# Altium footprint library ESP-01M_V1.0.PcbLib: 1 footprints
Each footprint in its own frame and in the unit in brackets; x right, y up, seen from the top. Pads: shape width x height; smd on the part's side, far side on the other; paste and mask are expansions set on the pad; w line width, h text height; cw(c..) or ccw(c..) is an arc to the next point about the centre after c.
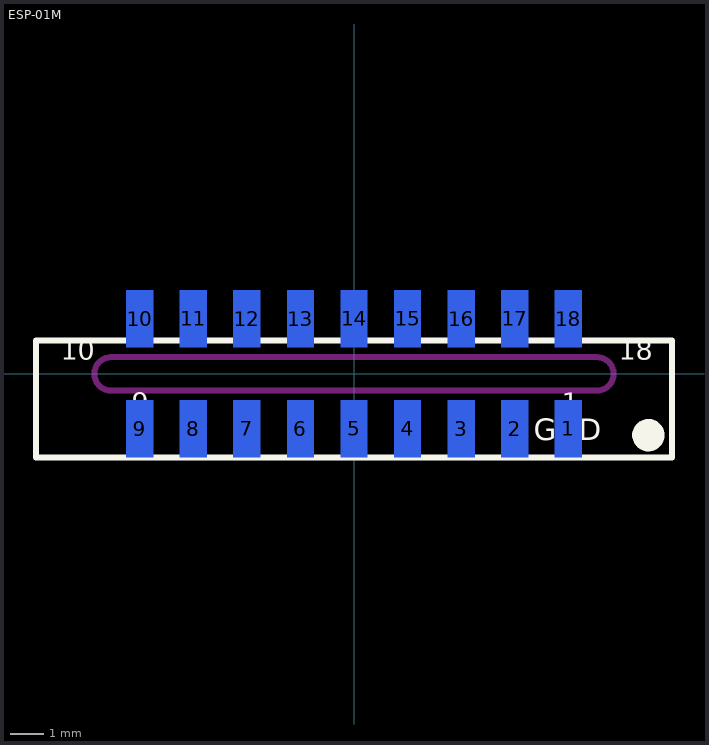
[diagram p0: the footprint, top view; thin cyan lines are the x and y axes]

## ESP-01M [mm]
pads (18):
  rect 0.8x1.7 smd far side: 1(6.4,-1.643) 2(4.8,-1.643) 3(3.2,-1.643) 4(1.6,-1.643) 5(0,-1.643) 6(-1.6,-1.643) 7(-3.2,-1.643) 8(-4.8,-1.643) 9(-6.4,-1.643) 10(-6.4,1.643) 11(-4.8,1.643) 12(-3.2,1.643) 13(-1.6,1.643) 14(0,1.643) 15(1.6,1.643) 16(3.2,1.643) 17(4.8,1.643) 18(6.4,1.643)
Top Overlay:
  circle w0.5: c8.788,-1.829 r0.234
  lines w0.178: -9.5,-2.5 -9.5,1 9.5,1 9.5,-2.5 -9.5,-2.5
  text "18" at 7.899,0.229 h1
  text "10" at -8.763,0.229 h1
  text "9" at -6.629,-1.346 h1
  text "1" at 6.198,-1.346 h1
  text "GND" at 5.359,-2.21 h1.1
Keep-Out Layer:
  lines w0.178: -7.75,-0.008 ccw(c-7.254,-0.004) -7.25,-0.5 7.25,-0.5 ccw(c7.254,-0.004) 7.75,-0.008 ; -7.75,0.008 cw(c-7.254,0.004) -7.25,0.5 7.25,0.5 cw(c7.254,0.004) 7.75,0.008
